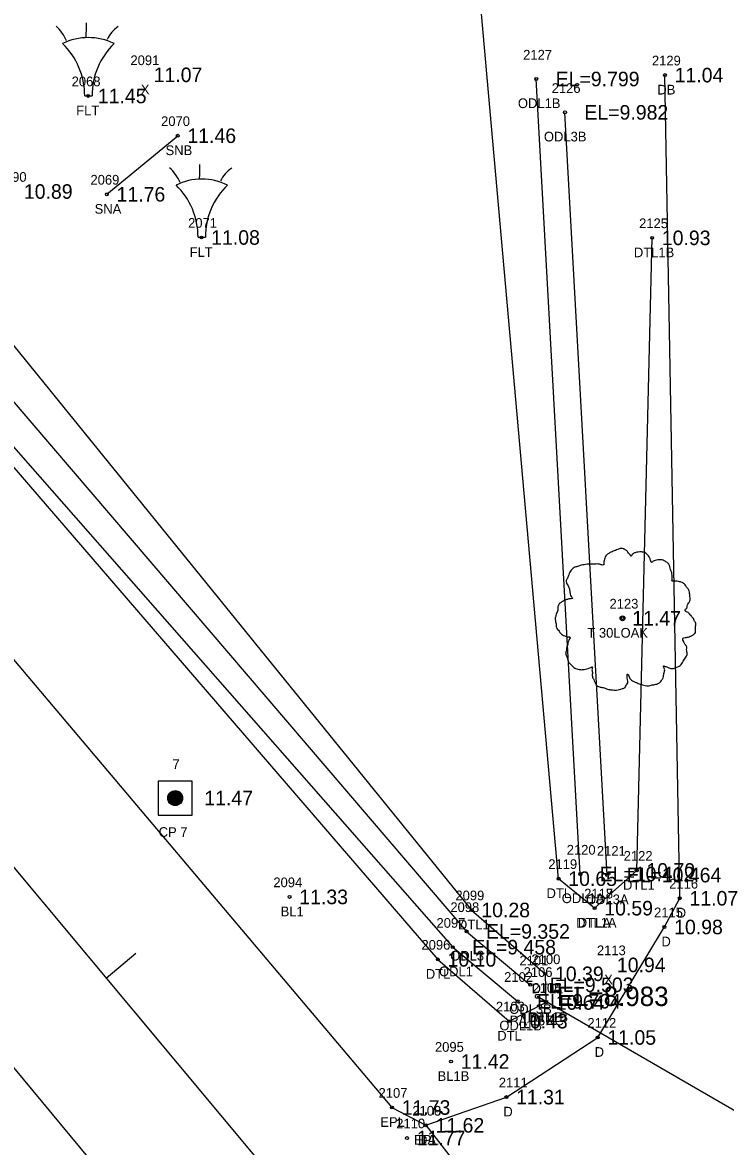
# Model space of a CAD drawing. Extents: x 2042117 to 2045853, y 303080 to 309569.
# Drawn here: x 2044293.7 to 2044366.1, y 304887 to 305002.9 of the extents above; entities that cross this region are included whole.
import ezdxf

# ---------------------------------------------------------------- set-up
doc = ezdxf.new("R2010")
doc.units = 0
for name, color, linetype in [('RD_DTM_BkLn_txCode', 7, 'Continuous'), ('RD_EX_BldgApp', 7, 'Continuous'), ('RD_EX_BldgApp_txCode', 7, 'Continuous'), ('RD_EX_DR_Pipe', 7, 'Continuous'), ('RD_EX_DR_Pipe_txCode', 7, 'Continuous'), ('RD_EX_Driveway', 7, 'Continuous'), ('RD_EX_Driveway_txCode', 7, 'Continuous'), ('RD_EX_H2O', 7, 'Continuous'), ('RD_EX_H2O_txCode', 7, 'Continuous'), ('RD_EX_Misc_txCode', 7, 'Continuous'), ('RD_EX_Road', 7, 'Continuous'), ('RD_EX_Road_txCode', 7, 'Continuous'), ('RD_EX_TX_BldgApp_ELEV', 7, 'Continuous'), ('RD_EX_TX_Driveway_ELEV', 7, 'Continuous'), ('RD_EX_TX_H2O_ELEV', 7, 'Continuous'), ('RD_EX_TX_Misc_ELEV', 7, 'Continuous'), ('RD_EX_TX_Road_ELEV', 7, 'Continuous'), ('RD_EX_TX_VEG_ELEV', 7, 'Continuous'), ('RD_EX_VEG', 7, 'Continuous'), ('RD_EX_VEG_txCode', 7, 'Continuous'), ('RD_HC_Cl', 7, 'Continuous'), ('RD_HC_Data_Tic', 7, 'Continuous'), ('RD_HC_Survey', 7, 'Continuous'), ('RD_HC_Survey_ELEV', 7, 'Continuous'), ('RD_HC_Survey_txCode', 7, 'Continuous'), ('RD_SMD_Locator', 7, 'Continuous'), ('RD_TX_Pipe_ElevEX', 7, 'Continuous')]:
    doc.layers.add(name, color=color, linetype=linetype)

msp = doc.modelspace()

# ---------------------------------------------------------------- linework, layer by layer
at = {"layer": 'RD_EX_BldgApp'}
for p, q in [((2044300.07, 304995.35), (2044300.82, 304995.35)), ((2044302.35, 304985.19), (2044309.65, 304991.23)), ((2044311.75, 304980.76), (2044312.5, 304980.76))]:
    msp.add_line(p, q, dxfattribs=at)
for centre, radius, start, end in [((2044293.75, 304998.99), 4.89, 24.3279, 46.2665), ((2044262.36, 305002.68), 37.88, 358.0671, 0.2715), ((2044305.33, 304999.74), 3.28, 123.2906, 154.4886), ((2044300.44, 304995.35), 6, 63.7794, 116.2206), ((2044292.57, 304995.35), 7.5, 0, 45.8366), ((2044308.32, 304995.35), 7.5, 134.1634, 180), ((2044305.44, 304984.4), 4.89, 24.3279, 46.2665), ((2044274.05, 304988.1), 37.88, 358.0671, 0.2715), ((2044317.02, 304985.15), 3.28, 123.2906, 154.4886), ((2044312.13, 304980.76), 6, 63.7794, 116.2206), ((2044304.25, 304980.76), 7.5, 0, 45.8366), ((2044320, 304980.76), 7.5, 134.1634, 180)]:
    msp.add_arc(centre, radius, start, end, dxfattribs=at)
at = {"layer": 'RD_EX_DR_Pipe'}
msp.add_line((2044346.71, 304902.5), (2044402.48, 304870.21), dxfattribs=at)
at = {"layer": 'RD_EX_Driveway'}
msp.add_lwpolyline([(2044335.22, 304889.2), (2044343.52, 304892.11), (2044352.93, 304898.26), (2044359.81, 304909.65), (2044361.39, 304912.61), (2044359.86, 304997.48)], dxfattribs=at)
at = {"layer": 'RD_EX_H2O'}
for p, q in [((2044351.13, 304915.11), (2044346.6, 304997.08)), ((2044353.91, 304915), (2044349.56, 304993.64))]:
    msp.add_line(p, q, dxfattribs=at)
for points in [[(2044033.22, 305275.98), (2044035.9, 305278.5), (2044040.04, 305277.28), (2044042.29, 305273.95), (2044048.6, 305260.29), (2044090.99, 305205.39), (2044151.22, 305127.18), (2044154.78, 305124.28), (2044202.92, 305070.22), (2044216.63, 305053.71), (2044279.58, 304974.12), (2044337.99, 304907.57), (2044344.68, 304901.99)], [(2044036.31, 305275.77), (2044038.93, 305275.76), (2044040.37, 305274.17), (2044045.78, 305258.87), (2044089.4, 305204.02), (2044149.36, 305125.44), (2044152.21, 305122.89), (2044203.11, 305065.8), (2044214.18, 305051.6), (2044278.81, 304973.18), (2044336.46, 304906.31), (2044343.82, 304899.94), (2044347.6, 304901.86)], [(2044052.64, 305262.28), (2044093.07, 305207.37), (2044155.92, 305130.37), (2044157.38, 305130.75), (2044170.33, 305147.63), (2044181.38, 305159.73), (2044197.15, 305188.95), (2044208.08, 305219.28), (2044210.72, 305219.24), (2044215.12, 305217.08), (2044202.83, 305184.83), (2044185.43, 305151.79), (2044169.6, 305138.4), (2044160.58, 305125.38), (2044211.54, 305068.64), (2044219.9, 305056.44), (2044285.19, 304978.84), (2044339.94, 304911.4), (2044347.53, 304904.82), (2044347.6, 304901.86)], [(2044211.75, 305214.4), (2044200.54, 305185.5), (2044183.75, 305152.21), (2044168.79, 305139.58), (2044158.66, 305124.96), (2044210.53, 305066.67), (2044218.51, 305055.53), (2044282.21, 304976.06), (2044339.42, 304909.19), (2044345.98, 304903.69)], [(2044352.61, 304911.59), (2044348.9, 304914.63), (2044340.38, 305010.38)], [(2044352.61, 304911.59), (2044356.95, 304915.48), (2044358.54, 304980.7)]]:
    msp.add_lwpolyline(points, dxfattribs=at)
at = {"layer": 'RD_EX_Road'}
for points in [[(2043522.11, 305820), (2043547.67, 305789.85), (2043610.72, 305713.32), (2043674.95, 305636.32), (2043738.18, 305559.62), (2043802.42, 305482.71), (2043865.72, 305405.84), (2043929.53, 305328.85), (2043994.13, 305253.28), (2044057.4, 305176.5), (2044121.27, 305100.2), (2044185.29, 305023.54), (2044249.56, 304947.28), (2044313.31, 304870.31), (2044377.09, 304793.29), (2044442, 304716.26), (2044505.92, 304639.55), (2044570.44, 304562.35), (2044634.61, 304485.93), (2044698.46, 304409.27), (2044762.46, 304332.37)], [(2043821.87, 305499.1), (2043885.81, 305423.07), (2043949.56, 305345.93), (2044013.41, 305270.34), (2044077.97, 305194.15), (2044141.4, 305117.67), (2044205.92, 305040.83), (2044269.54, 304964.65), (2044331.73, 304891.04), (2044335.22, 304889.2), (2044346.01, 304875.31), (2044356.18, 304867.61), (2044370.01, 304868.14), (2044386.83, 304866.36), (2044389.44, 304849.53), (2044390.71, 304830.73), (2044393.77, 304818.44), (2044395.5, 304814.18), (2044398.16, 304811.09)]]:
    msp.add_lwpolyline(points, dxfattribs=at)
at = {"layer": 'RD_EX_VEG'}
for centre, radius in [((2044355.49, 304941.48), 0.25), ((2044355.48, 304941.46), 0.0001)]:
    msp.add_circle(centre, radius, dxfattribs=at)
for points in [[(2044355.63, 304948.64), (2044355.33, 304948.67), (2044355, 304948.57), (2044354.75, 304948.47), (2044354.53, 304948.39), (2044354.3, 304948.29), (2044354, 304948.12), (2044353.78, 304947.92), (2044353.65, 304947.67), (2044353.6, 304947.45), (2044353.55, 304947.17), (2044353.55, 304947), (2044353.43, 304946.97), (2044353.28, 304947), (2044353.03, 304947.07), (2044352.78, 304947.07), (2044352.53, 304947.07), (2044352.18, 304947.05), (2044351.83, 304947.05), (2044351.55, 304947), (2044351.23, 304946.95), (2044350.85, 304946.82), (2044350.5, 304946.7), (2044350.2, 304946.45), (2044349.95, 304945.97), (2044349.83, 304945.62), (2044349.68, 304945.37), (2044349.83, 304944.92), (2044350, 304944.57), (2044350.03, 304944.37), (2044350.1, 304943.95), (2044350.2, 304943.72), (2044350.33, 304943.52), (2044350.25, 304943.5), (2044349.88, 304943.45), (2044349.58, 304943.35), (2044349.15, 304943.12), (2044348.93, 304942.9), (2044348.83, 304942.57), (2044348.8, 304942.22), (2044348.7, 304942.02), (2044348.63, 304941.75), (2044348.6, 304941.67), (2044348.55, 304941.35), (2044348.65, 304940.9), (2044348.68, 304940.55), (2044348.8, 304940.32), (2044348.95, 304940.15), (2044349.13, 304939.9), (2044349.53, 304939.67), (2044349.85, 304939.57), (2044350.05, 304939.55), (2044349.88, 304939.05), (2044349.83, 304938.7), (2044349.7, 304938.3), (2044349.7, 304938.22), (2044349.65, 304937.75), (2044349.8, 304937.42), (2044349.88, 304937.05), (2044350.05, 304936.82), (2044350.33, 304936.53), (2044350.65, 304936.3), (2044351.15, 304936.18), (2044351.55, 304936.2), (2044352.13, 304936.38), (2044352.38, 304936.45), (2044352.35, 304936.28), (2044352.38, 304935.9), (2044352.38, 304935.48), (2044352.53, 304935.15), (2044352.63, 304934.88), (2044352.78, 304934.63), (2044353.1, 304934.4), (2044353.5, 304934.33), (2044353.93, 304934.18), (2044354.38, 304934.1), (2044354.88, 304934.08), (2044355.48, 304934.23), (2044355.75, 304934.35), (2044355.85, 304934.53), (2044356.05, 304934.9), (2044356, 304935.13), (2044356.03, 304935.73), (2044356.13, 304935.55), (2044356.3, 304935.2), (2044356.8, 304934.9), (2044357.2, 304934.73), (2044357.68, 304934.58), (2044357.98, 304934.5), (2044358.45, 304934.58), (2044358.82, 304934.65), (2044359.2, 304934.78), (2044359.5, 304935.05), (2044359.67, 304935.33), (2044359.72, 304935.6), (2044359.8, 304935.98), (2044359.85, 304936.15)], [(2044359.85, 304936.15), (2044359.77, 304936.33), (2044359.72, 304936.58), (2044359.8, 304936.55), (2044359.97, 304936.5), (2044360.25, 304936.38), (2044360.47, 304936.3), (2044360.8, 304936.33), (2044361.07, 304936.43), (2044361.52, 304936.7), (2044361.8, 304937.17), (2044362.07, 304937.57), (2044362.15, 304937.9), (2044362.1, 304938.12), (2044362.07, 304938.62), (2044361.87, 304938.87), (2044361.82, 304939), (2044361.72, 304939.4), (2044361.8, 304939.45), (2044362.07, 304939.5), (2044362.45, 304939.62), (2044362.72, 304939.75), (2044362.95, 304939.92), (2044363.02, 304940.15), (2044363, 304940.55), (2044363.05, 304940.95), (2044362.97, 304941.1), (2044362.87, 304941.25), (2044362.8, 304941.45), (2044362.65, 304941.6), (2044362.55, 304941.75), (2044362.45, 304941.85), (2044362.32, 304942), (2044362.15, 304942.12), (2044362, 304942.17), (2044361.95, 304942.32), (2044362.1, 304942.52), (2044362.15, 304942.62), (2044362.17, 304942.85), (2044362.4, 304943.2), (2044362.45, 304943.6), (2044362.4, 304944.02), (2044362.35, 304944.3), (2044362.2, 304944.57), (2044362, 304944.82), (2044361.87, 304945), (2044361.7, 304945.12), (2044361.37, 304945.25), (2044361.12, 304945.3), (2044360.77, 304945.3), (2044360.57, 304945.35), (2044360.6, 304945.4), (2044360.6, 304945.55), (2044360.6, 304945.82), (2044360.52, 304946.27), (2044360.37, 304946.77), (2044360.37, 304946.8), (2044360.27, 304947.05), (2044360.05, 304947.25), (2044359.87, 304947.35), (2044359.67, 304947.47), (2044359.42, 304947.5), (2044359.12, 304947.5), (2044358.85, 304947.45), (2044358.65, 304947.35), (2044358.48, 304947.22), (2044358.4, 304947.37), (2044358.3, 304947.67), (2044358.25, 304947.82), (2044358.1, 304947.99), (2044357.88, 304948.19), (2044357.43, 304948.32), (2044356.8, 304948.24), (2044356.5, 304948.04), (2044356.35, 304947.87), (2044356.3, 304947.99), (2044356.1, 304948.19), (2044356, 304948.37), (2044355.83, 304948.49), (2044355.68, 304948.59), (2044355.58, 304948.64)]]:
    msp.add_spline(points, degree=3, dxfattribs=at)
at = {"layer": 'RD_HC_Cl'}
msp.add_line((2043284.3, 306123.24), (2045221.31, 303804), dxfattribs=at)
at = {"layer": 'RD_HC_Data_Tic'}
msp.add_line((2044302.28, 304904.38), (2044305.35, 304906.94), dxfattribs=at)
at = {"layer": 'RD_HC_Survey'}
for p, q in [((2044309.07, 304922.24), (2044309.07, 304923.64)), ((2044309.09, 304922.23), (2044309.09, 304923.65)), ((2044309.11, 304922.22), (2044309.11, 304923.66)), ((2044309.14, 304922.21), (2044309.14, 304923.67)), ((2044309.16, 304922.2), (2044309.16, 304923.67)), ((2044309.19, 304922.2), (2044309.19, 304923.68)), ((2044309.21, 304922.19), (2044309.21, 304923.69)), ((2044309.24, 304922.19), (2044309.24, 304923.69)), ((2044309.26, 304922.18), (2044309.26, 304923.7)), ((2044309.29, 304922.18), (2044309.29, 304923.7)), ((2044309.31, 304922.17), (2044309.31, 304923.7)), ((2044309.34, 304922.17), (2044309.34, 304923.71)), ((2044309.36, 304922.17), (2044309.36, 304923.71)), ((2044309.39, 304922.17), (2044309.39, 304923.71)), ((2044309.41, 304922.17), (2044309.41, 304923.71)), ((2044309.44, 304922.17), (2044309.44, 304923.71)), ((2044309.46, 304922.17), (2044309.46, 304923.71)), ((2044309.49, 304922.18), (2044309.49, 304923.7)), ((2044309.51, 304922.18), (2044309.51, 304923.7)), ((2044309.54, 304922.18), (2044309.54, 304923.7)), ((2044309.56, 304922.19), (2044309.56, 304923.69)), ((2044309.58, 304922.19), (2044309.58, 304923.68)), ((2044309.61, 304922.2), (2044309.61, 304923.68)), ((2044309.63, 304922.21), (2044309.63, 304923.67)), ((2044309.66, 304922.22), (2044309.66, 304923.66)), ((2044309.68, 304922.23), (2044309.68, 304923.65)), ((2044309.71, 304922.24), (2044309.71, 304923.64)), ((2044309.73, 304922.25), (2044309.73, 304923.63)), ((2044308.64, 304922.76), (2044308.64, 304923.12)), ((2044308.67, 304922.68), (2044308.67, 304923.2)), ((2044308.69, 304922.62), (2044308.69, 304923.26)), ((2044308.72, 304922.57), (2044308.72, 304923.31)), ((2044308.74, 304922.53), (2044308.74, 304923.35)), ((2044308.77, 304922.49), (2044308.77, 304923.39)), ((2044308.79, 304922.46), (2044308.79, 304923.42)), ((2044308.82, 304922.43), (2044308.82, 304923.45)), ((2044308.84, 304922.4), (2044308.84, 304923.48)), ((2044308.87, 304922.38), (2044308.87, 304923.5)), ((2044308.89, 304922.36), (2044308.89, 304923.52)), ((2044308.92, 304922.34), (2044308.92, 304923.54)), ((2044308.94, 304922.32), (2044308.94, 304923.56)), ((2044308.97, 304922.3), (2044308.97, 304923.58)), ((2044308.99, 304922.28), (2044308.99, 304923.6)), ((2044309.02, 304922.27), (2044309.02, 304923.61)), ((2044309.04, 304922.26), (2044309.04, 304923.62)), ((2044309.76, 304922.26), (2044309.76, 304923.62)), ((2044309.78, 304922.28), (2044309.78, 304923.6)), ((2044309.81, 304922.29), (2044309.81, 304923.59)), ((2044309.83, 304922.31), (2044309.83, 304923.57)), ((2044309.86, 304922.33), (2044309.86, 304923.55)), ((2044309.88, 304922.35), (2044309.88, 304923.53)), ((2044309.91, 304922.37), (2044309.91, 304923.51)), ((2044309.93, 304922.39), (2044309.93, 304923.49)), ((2044309.96, 304922.42), (2044309.96, 304923.46)), ((2044309.98, 304922.44), (2044309.98, 304923.44)), ((2044310.01, 304922.47), (2044310.01, 304923.4)), ((2044310.03, 304922.51), (2044310.03, 304923.37)), ((2044310.06, 304922.55), (2044310.06, 304923.33)), ((2044310.08, 304922.59), (2044310.08, 304923.29)), ((2044310.1, 304922.65), (2044310.1, 304923.23)), ((2044310.13, 304922.72), (2044310.13, 304923.16)), ((2044310.15, 304922.83), (2044310.15, 304923.05))]:
    msp.add_line(p, q, dxfattribs=at)
msp.add_lwpolyline([(2044311.14, 304924.69), (2044307.64, 304924.69), (2044307.64, 304921.19), (2044311.14, 304921.19)], close=True, dxfattribs=at)
msp.add_circle((2044309.39, 304922.94), 0.769, dxfattribs=at)
at = {"layer": 'RD_SMD_Locator'}
for centre, radius in [((2044346.6, 304997.08), 0.15), ((2044359.86, 304997.48), 0.15), ((2044300.42, 304995.33), 0.15), ((2044349.56, 304993.64), 0.15), ((2044309.65, 304991.23), 0.15), ((2044302.35, 304985.19), 0.15), ((2044312.1, 304980.74), 0.15), ((2044358.54, 304980.7), 0.15), ((2044355.49, 304941.48), 0.15), ((2044309.39, 304922.94), 0.15), ((2044356.95, 304915.48), 0.15), ((2044348.9, 304914.63), 0.15), ((2044351.13, 304915.11), 0.15), ((2044353.91, 304915), 0.15), ((2044321.18, 304912.75), 0.15), ((2044361.39, 304912.61), 0.15), ((2044339.94, 304911.4), 0.15), ((2044352.61, 304911.59), 0.15), ((2044352.61, 304911.59), 0.15), ((2044359.81, 304909.65), 0.15), ((2044339.42, 304909.19), 0.15), ((2044337.99, 304907.57), 0.15), ((2044336.46, 304906.31), 0.15), ((2044347.53, 304904.82), 0.15), ((2044345.98, 304903.69), 0.15), ((2044344.68, 304901.99), 0.15), ((2044346.71, 304902.5), 0.2), ((2044347.6, 304901.86), 0.15), ((2044347.6, 304901.86), 0.15), ((2044343.82, 304899.94), 0.15), ((2044352.93, 304898.26), 0.15), ((2044337.82, 304895.78), 0.15), ((2044331.73, 304891.04), 0.15), ((2044343.52, 304892.11), 0.15), ((2044335.22, 304889.2), 0.15), ((2044335.22, 304889.2), 0.15), ((2044333.28, 304887.89), 0.15)]:
    msp.add_circle(centre, radius, dxfattribs=at)

# ---------------------------------------------------------------- texts
at = {"layer": 'RD_DTM_BkLn_txCode'}
for s, p in [('2094', (2044319.51, 304913.75)), ('BL1', (2044320.26, 304910.75)), ('2095', (2044336.16, 304896.78)), ('BL1B', (2044336.43, 304893.78)), ('2110', (2044332.17, 304888.89))]:
    msp.add_text(s, height=1, dxfattribs=at).set_placement(p)
at = {"layer": 'RD_EX_BldgApp_txCode'}
for s, p in [('2068', (2044298.72, 304996.33)), ('FLT', (2044299.19, 304993.33)), ('2070', (2044307.94, 304992.23)), ('SNB', (2044308.4, 304989.23)), ('2069', (2044300.66, 304986.19)), ('SNA', (2044301.09, 304983.19)), ('2071', (2044310.72, 304981.74)), ('FLT', (2044310.88, 304978.74))]:
    msp.add_text(s, height=1, dxfattribs=at).set_placement(p)
at = {"layer": 'RD_EX_DR_Pipe_txCode'}
for s, p in [('2106', (2044345.3, 304904.5)), ('PA 15RC', (2044343.87, 304899.5))]:
    msp.add_text(s, height=1, dxfattribs=at).set_placement(p)
at = {"layer": 'RD_EX_Driveway_txCode'}
for s, p in [('2129', (2044358.52, 304998.48)), ('DB', (2044359.08, 304995.48)), ('2116', (2044360.3, 304913.61)), ('2115', (2044358.74, 304910.65)), ('D', (2044361.08, 304910.61)), ('D', (2044359.5, 304907.65)), ('2112', (2044351.87, 304899.26)), ('D', (2044352.62, 304896.26)), ('2111', (2044342.74, 304893.11)), ('2109', (2044333.83, 304890.2)), ('D', (2044343.21, 304890.11)), ('DA', (2044334.42, 304887.2))]:
    msp.add_text(s, height=1, dxfattribs=at).set_placement(p)
at = {"layer": 'RD_EX_H2O_txCode'}
for s, p in [('2127', (2044345.25, 304999.08)), ('2126', (2044348.19, 304995.64)), ('ODL1B', (2044344.71, 304994.08)), ('ODL3B', (2044347.39, 304990.64)), ('2125', (2044357.2, 304981.7)), ('DTL1B', (2044356.66, 304978.7)), ('2120', (2044349.74, 304917.11)), ('2121', (2044352.85, 304917)), ('2122', (2044355.61, 304916.48)), ('2119', (2044347.84, 304915.63)), ('DTL1', (2044355.54, 304913.48)), ('2099', (2044338.27, 304912.4)), ('DTL', (2044347.66, 304912.63)), ('2117', (2044351.54, 304912.59)), ('2118', (2044351.54, 304912.59)), ('2098', (2044337.75, 304911.19)), ('ODL1A', (2044349.23, 304912.11)), ('ODL3A', (2044351.73, 304912)), ('2097', (2044336.32, 304909.57)), ('DTL1', (2044338.53, 304909.4)), ('DTL1A', (2044350.71, 304909.59)), ('DTLA', (2044350.88, 304909.59)), ('2096', (2044334.77, 304907.31)), ('ODL3', (2044337.73, 304906.19)), ('2101', (2044344.87, 304905.69)), ('2100', (2044346.11, 304905.82)), ('DTL', (2044335.22, 304904.31)), ('ODL1', (2044336.58, 304904.57)), ('2102', (2044343.29, 304903.99)), ('DTL1', (2044346.12, 304902.82)), ('2104', (2044346.21, 304902.86)), ('2105', (2044346.21, 304902.86)), ('2103', (2044342.44, 304900.94)), ('ODL3B', (2044343.81, 304900.69)), ('DTL1B', (2044345.71, 304899.86)), ('DTLB', (2044345.88, 304899.86)), ('ODL1B', (2044342.8, 304898.99)), ('DTL', (2044342.58, 304897.94))]:
    msp.add_text(s, height=1, dxfattribs=at).set_placement(p)
at = {"layer": 'RD_EX_Misc_txCode'}
for s, p in [('2091', (2044304.78, 304998.51)), ('X', (2044305.85, 304995.51)), ('2090', (2044291.1, 304986.48)), ('2113', (2044352.85, 304906.74)), ('X', (2044353.6, 304903.74))]:
    msp.add_text(s, height=1, dxfattribs=at).set_placement(p)
at = {"layer": 'RD_EX_Road_txCode'}
for s, p in [('2107', (2044330.35, 304892.04)), ('2108', (2044333.83, 304890.2)), ('EPL', (2044330.53, 304889.04)), ('EPL', (2044334.01, 304887.2))]:
    msp.add_text(s, height=1, dxfattribs=at).set_placement(p)
at = {"layer": 'RD_EX_TX_BldgApp_ELEV'}
for s, p in [('11.45', (2044301.42, 304994.58)), ('11.46', (2044310.65, 304990.48)), ('11.76', (2044303.35, 304984.44)), ('11.08', (2044313.1, 304979.99))]:
    msp.add_text(s, height=1.5, dxfattribs=at).set_placement(p)
at = {"layer": 'RD_EX_TX_Driveway_ELEV'}
for s, p in [('11.04', (2044360.86, 304996.73)), ('11.07', (2044362.39, 304911.86)), ('10.98', (2044360.81, 304908.9)), ('11.05', (2044353.93, 304897.51)), ('11.31', (2044344.52, 304891.36)), ('11.62', (2044336.22, 304888.45))]:
    msp.add_text(s, height=1.5, dxfattribs=at).set_placement(p)
at = {"layer": 'RD_EX_TX_H2O_ELEV'}
for s, p in [('EL=9.799', (2044348.6, 304996.33)), ('EL=9.982', (2044351.56, 304992.89)), ('10.93', (2044359.54, 304979.95)), ('EL=10.412', (2044353.13, 304914.36)), ('EL=10.464', (2044355.91, 304914.25)), ('10.70', (2044357.95, 304914.73)), ('10.65', (2044349.9, 304913.88)), ('10.28', (2044340.94, 304910.65)), ('10.59', (2044353.61, 304910.84)), ('10.59', (2044353.61, 304910.84)), ('EL=9.352', (2044341.42, 304908.44)), ('EL=9.458', (2044339.99, 304906.82)), ('10.10', (2044337.46, 304905.56)), ('10.39', (2044348.53, 304904.07)), ('EL=9.503', (2044347.98, 304902.94)), ('EL=9.704', (2044346.68, 304901.24)), ('10.64', (2044348.6, 304901.11)), ('10.64', (2044348.6, 304901.11)), ('10.43', (2044344.82, 304899.19))]:
    msp.add_text(s, height=1.5, dxfattribs=at).set_placement(p)
at = {"layer": 'RD_EX_TX_Misc_ELEV'}
for s, p in [('11.07', (2044307.17, 304996.76)), ('10.89', (2044293.8, 304984.73)), ('11.33', (2044322.18, 304912)), ('10.94', (2044354.91, 304904.99)), ('11.42', (2044338.82, 304895.03)), ('11.77', (2044334.28, 304887.14))]:
    msp.add_text(s, height=1.5, dxfattribs=at).set_placement(p)
at = {"layer": 'RD_EX_TX_Road_ELEV'}
for s, p in [('11.73', (2044332.73, 304890.29)), ('11.62', (2044336.22, 304888.45))]:
    msp.add_text(s, height=1.5, dxfattribs=at).set_placement(p)
at = {"layer": 'RD_EX_TX_VEG_ELEV'}
msp.add_text('11.47', height=1.5, dxfattribs=at).set_placement((2044356.49, 304940.73))
at = {"layer": 'RD_EX_VEG_txCode'}
for s, p in [('2123', (2044354.15, 304942.48)), ('T 30LOAK', (2044351.87, 304939.48))]:
    msp.add_text(s, height=1, dxfattribs=at).set_placement(p)
at = {"layer": 'RD_HC_Survey_ELEV'}
msp.add_text('11.47', height=1.5, dxfattribs=at).set_placement((2044312.39, 304922.19))
at = {"layer": 'RD_HC_Survey_txCode'}
for s, p in [('7', (2044309.11, 304925.94)), ('CP 7', (2044307.69, 304918.94))]:
    msp.add_text(s, height=1, dxfattribs=at).set_placement(p)
at = {"layer": 'RD_TX_Pipe_ElevEX'}
msp.add_text('EL=8.983', height=2, dxfattribs=at).set_placement((2044348.71, 304901.5))

doc.saveas('drawing.dxf')
